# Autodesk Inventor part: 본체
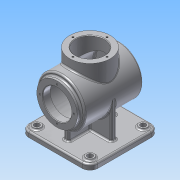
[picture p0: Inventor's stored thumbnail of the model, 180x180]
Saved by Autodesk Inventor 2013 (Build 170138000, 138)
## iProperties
Created: 2015-07
Part Number: 본체
Material: 알루미늄 6061
Document SubType Name: Modeling
Designer: ST4
Density: 2.71 g/cm^3
Mass: 1277.5 g
Surface Area: 1267.94 cm^2
Volume: 471.402 cm^3
Author: ST4
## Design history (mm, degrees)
sketch "스케치2"
  geometry: L1 (-55, 0)-(55, 0); L2 (-62, 27)-(-48, 27); L3 (-48, 27)-(-48, 37); L4 (-45, 40)-(45, 40); L5 (48, 37)-(48, 0); L6 (55, 0)-(55, 45); L7 (55, 45)-(-55, 45); L8 (-55, 45)-(-55, 38); L9 (-55, 38)-(-62, 38); L10 (-62, 38)-(-62, 27); A1 r 3 centre (-45, 37) between (-45, 40) and (-48, 37); A2 r 3 centre (45, 37) between (48, 37) and (45, 40); 2 further points
  constraints: 20 end point, 6 parallel, 4 point on circle, 4 tangent, 3 perpendicular, 2 centre point, 2 point on line, 1 coincident, 1 equal radius, 1 horizontal, 1 midpoint
  dimensions: "d0" = 110 distance of L1.start L1.end; "d2" = 90 diameter of L7 L1; "d3" = 7 distance of L8.end L9.end; "d4" = 7 distance between parallel lines of L5 L6; "d5" = 54 diameter of L2 L1; "d6" = 76 diameter of L9 L1; "d7" = 80 diameter of L4 L1; "d8" = 7 distance between parallel lines of L3 L8 (= d3); "d9" = 3 radius of A1
revolve "회전1" sketch "스케치2" stored, may be unused: angle "d10" = 90 deg
node "작업 평면1"
sketch "스케치3"
  geometry: L1 (-65, -65)-(65, -65); L2 (65, -65)-(65, 65); L3 (65, 65)-(-65, 65); L4 (-65, 65)-(-65, -65); L5 (-65, -65)-(65, 65); L6 (65, -65)-(-65, 65); 1 further point
  constraints: 12 end point, 2 midpoint, 2 parallel, 2 perpendicular, 1 horizontal
  dimensions: "d12" = 130 distance of L2.end L3.end
extrude "돌출1" join sketch "스케치3" distance "d14" = 10; taper "d15" = 0 deg
sketch "스케치4"
  geometry: L1 (65, -68)-(-65, -68) reference; L2 (-45, 0)-(-45, -68); L3 (45, 0)-(45, -68); A1 r 45 centre (0, 0) between (-45, 0) and (45, 0) reference; 1 further point
  constraints: 4 end point, 2 perpendicular, 2 point on circle, 2 point on line, 2 tangent
extrude "돌출2" join sketch "스케치4" stored distance "d16" = 10; taper "d17" = 0 deg
sketch "스케치5"
  geometry: L1 (-55, -45)-(55, -45) reference; L2 (65, -68)-(-65, -68) reference; L3 (-45, -45)-(-45, -68); 1 further point
  constraints: 2 end point, 2 point on line, 1 perpendicular
  dimensions: "d18" = 45 distance from line of L3 point (0, 0)
feature "리브1" sketch "스케치5" dims "d19" = 1, "d20" = 10, "d21" = 0, "d22" = 0, "d23" = 1, "d24" = 1
node "작업 평면2"
sketch "스케치6"
  geometry: C1 r 38 at (0, 0); 1 further point
  constraints: 1 centre point, 1 coincident
  dimensions: "d26" = 76 diameter of C1
extrude "돌출3" join sketch "스케치6" stored distance "d28" = 10; taper "d29" = 0 deg
hole "구멍1" diameter "d32" = 54; stored, may be unused: countersink angle "d36" = 90 deg, drill point angle "d38" = 0 deg; dims "d30" = 10, "d31" = 10, "d33" = 6, "d34" = 4, "d35" = 2, "d37" = 50
sketch "스케치7"
  geometry: C1 r 45 at (0, 0) reference; 1 further point
  constraints: 1 coincident, 1 other
feature "엠보싱1" sketch "스케치7" dims "d0" = 110, "d2" = 90, "d3" = 7, "d4" = 7, "d5" = 54, "d6" = 76, "d7" = 80, "d8" = 7 (= d3), "d9" = 3, "d39" = 0.5, "d40" = 0
fillet "모깎기1" dims "d41" = 15, "d42" = 3
fillet "모깎기2" dims "d43" = 3
chamfer "모따기1" distance "d44" = 1; stored, may be unused: second distance "d45" = 2, angle "d46" = 45 deg
sketch "스케치8"
  geometry: C1 r 38 at (0, 0) reference; 1 further point
  constraints: 1 vertical alignment
  dimensions: "d47" = 32 distance of point (0, 32) C1.centre
hole "구멍2" sketch "스케치8" at (0, 32) diameter "d48" = 3.242; stored, may be unused: countersink angle "d52" = 90 deg, drill point angle "d54" = 118 deg; dims "d49" = 8, "d50" = 4, "d51" = 2, "d53" = 10
sketch "스케치9"
  geometry: C1 r 38 at (0, 0) reference; 1 further point
  constraints: 1 horizontal alignment
  dimensions: "d58" = 32 distance of C1.centre point (-32, 0)
hole "구멍3" sketch "스케치9" at (-32, 0) diameter "d59" = 3.242; stored, may be unused: countersink angle "d63" = 90 deg, drill point angle "d65" = 118 deg; dims "d60" = 8, "d61" = 4, "d62" = 2, "d64" = 10
sketch "스케치10"
  geometry: C1 r 5 at (-50, 50); C2 r 7.5 at (-50, 50); A1 r 12 centre (-50, 50) between (-50, 62) and (-62, 50) reference; 1 further point
  constraints: 2 centre point, 2 coincident
  dimensions: "d69" = 10 diameter of C1; "d71" = 15 diameter of C2
extrude "돌출4" join sketch "스케치10" distance "d72" = 3; taper "d73" = 0 deg
extrude "돌출5" cut sketch "스케치10" stored distance "d74" = 3; taper "d75" = 0 deg
fillet "모깎기3" dims "d82" = 3
node "솔리드1"
mirror "대칭1"
pattern_circular "원형 패턴1" dims angle "d56" = 360 deg
pattern_circular "원형 패턴2" dims angle "d67" = 360 deg
pattern_linear "직사각형 패턴1"
other parameters: "d11" = -78
